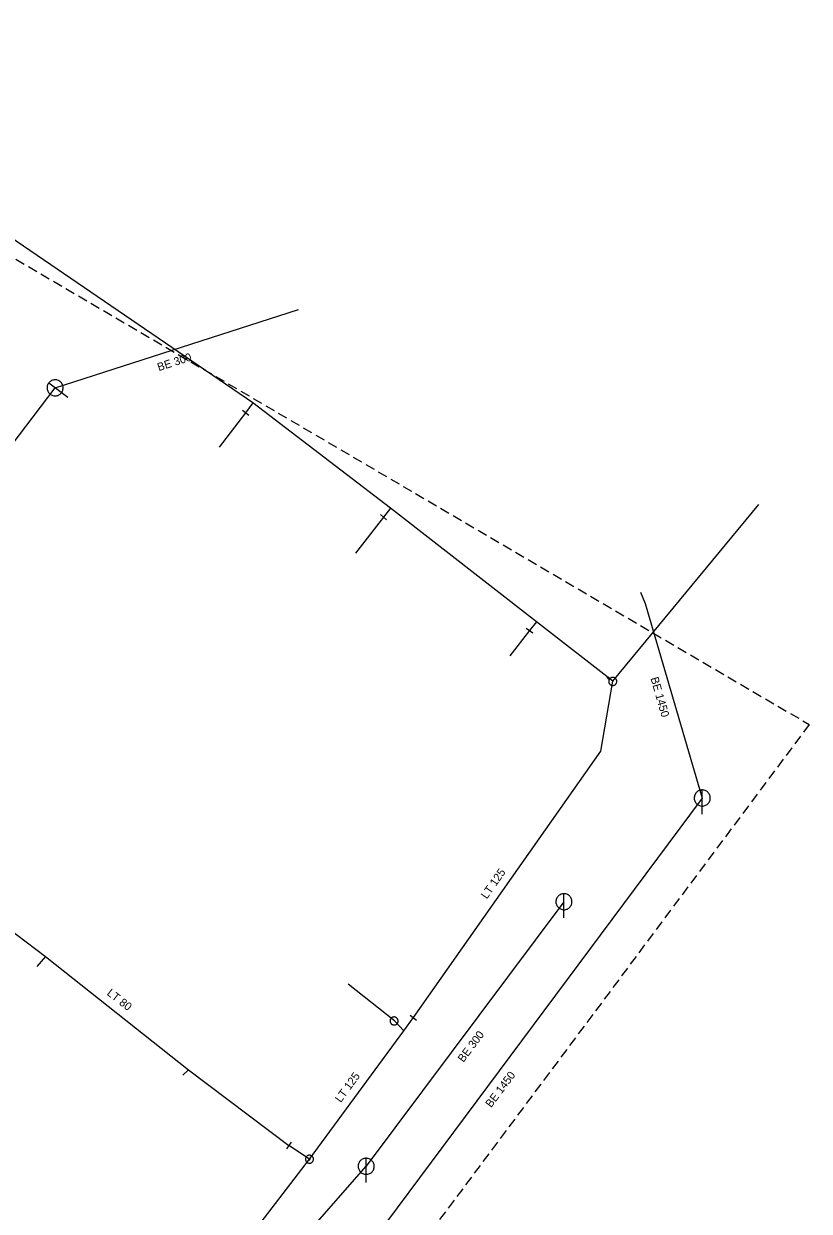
# Model space of a CAD drawing. Extents: x -791337 to -790755, y -988454 to -987923.
# Drawn here: x -790852.8 to -790755.1, y -988262.8 to -988115.1 of the extents above; entities that cross this region are included whole.
import ezdxf

# ---------------------------------------------------------------- set-up
doc = ezdxf.new("R2010")
doc.units = 0
doc.header["$LTSCALE"] = 0.4
doc.linetypes.add('MEDIUM_DASHED', pattern=[4.5, 3, -1.5])
for name, color, linetype, lineweight in [('1', 7, 'Continuous', 13), ('13', 7, 'Continuous', 13), ('14', 7, 'Continuous', 25), ('17', 7, 'Continuous', 25), ('22', 7, 'Continuous', 13), ('23', 7, 'Continuous', 13), ('34', 7, 'Continuous', 13), ('47', 7, 'Continuous', 13), ('63', 7, 'MEDIUM_DASHED', 25)]:
    doc.layers.add(name, color=color, linetype=linetype, lineweight=lineweight)

msp = doc.modelspace()

# ---------------------------------------------------------------- linework, layer by layer
at = {"layer": '13'}
for p, q in [((-790824.261, -988162.25), (-790825.189, -988163.508)), ((-790825.189, -988163.508), (-790828.463, -988167.789)), ((-790808.039, -988176.499), (-790811.535, -988180.96)), ((-790807.158, -988175.363), (-790808.039, -988176.499)), ((-790789.015, -988189.477), (-790789.888, -988190.568)), ((-790789.888, -988190.568), (-790792.35, -988193.728)), ((-790850.055, -988231.078), (-790851.113, -988232.317)), ((-790832.26, -988245.158), (-790832.993, -988245.852))]:
    msp.add_line(p, q, dxfattribs=at)
msp.add_lwpolyline([(-790805.532, -988240.335), (-790806.689, -988239.099), (-790812.443, -988234.541)], dxfattribs=at)
at = {"layer": '14'}
for p, q in [((-790848.859, -988160.41), (-790818.585, -988150.648)), ((-790872.25, -988191.129), (-790848.859, -988160.41)), ((-790768.42, -988211.39), (-790819.92, -988280.52)), ((-790785.61, -988224.28), (-790810.19, -988257.17)), ((-790834.989, -988285.46), (-790810.19, -988257.17))]:
    msp.add_line(p, q, dxfattribs=at)
at = {"layer": '14', "lineweight": 13}
msp.add_line((-790817.244, -988256.29), (-790819.799, -988254.598), dxfattribs=at)
at = {"layer": '14'}
msp.add_lwpolyline([(-790776.109, -988185.784), (-790775.515, -988187.214), (-790768.42, -988211.39)], dxfattribs=at)
at = {"layer": '17'}
for p, q in [((-790779.549, -988196.869), (-790761.405, -988174.91)), ((-790834.335, -988278.502), (-790817.244, -988256.29))]:
    msp.add_line(p, q, dxfattribs=at)
for points in [[(-790779.549, -988196.869), (-790789.015, -988189.477), (-790807.158, -988175.363), (-790824.261, -988162.25), (-790868.789, -988131.909)], [(-790804.318, -988238.685), (-790781.01, -988205.579), (-790779.549, -988196.869)], [(-790865.725, -988219.221), (-790850.055, -988231.078), (-790832.26, -988245.158), (-790819.799, -988254.598)], [(-790817.244, -988256.29), (-790805.532, -988240.335), (-790804.318, -988238.685)]]:
    msp.add_lwpolyline(points, dxfattribs=at)
at = {"layer": '22'}
for p, q in [((-790847.261, -988161.613), (-790849.657, -988159.808)), ((-790768.42, -988213.39), (-790768.419, -988210.39)), ((-790785.61, -988226.28), (-790785.609, -988223.28)), ((-790810.19, -988259.17), (-790810.189, -988256.17))]:
    msp.add_line(p, q, dxfattribs=at)
for points in [[(-790848.256, -988159.611), (-790848.347, -988159.55), (-790848.444, -988159.5), (-790848.547, -988159.46), (-790848.652, -988159.431), (-790848.76, -988159.414), (-790848.87, -988159.41), (-790848.979, -988159.417), (-790849.086, -988159.437), (-790849.192, -988159.467), (-790849.293, -988159.509), (-790849.389, -988159.562), (-790849.478, -988159.626), (-790849.56, -988159.698), (-790849.634, -988159.779), (-790849.698, -988159.868), (-790849.752, -988159.963), (-790849.797, -988160.063), (-790849.829, -988160.168), (-790849.849, -988160.276), (-790849.858, -988160.384), (-790849.854, -988160.494), (-790849.839, -988160.602), (-790849.812, -988160.709), (-790849.774, -988160.811), (-790849.725, -988160.909), (-790849.665, -988161), (-790849.595, -988161.085), (-790849.517, -988161.162), (-790849.43, -988161.229), (-790849.337, -988161.287), (-790849.239, -988161.335), (-790849.136, -988161.37), (-790849.029, -988161.395), (-790848.92, -988161.408), (-790848.81, -988161.409), (-790848.702, -988161.398), (-790848.595, -988161.375), (-790848.491, -988161.34), (-790848.392, -988161.295), (-790848.297, -988161.238), (-790848.21, -988161.172), (-790848.131, -988161.097), (-790848.06, -988161.012), (-790847.999, -988160.922), (-790847.949, -988160.825), (-790847.909, -988160.723), (-790847.88, -988160.617), (-790847.863, -988160.508), (-790847.858, -988160.399), (-790847.865, -988160.29), (-790847.884, -988160.182), (-790847.915, -988160.077), (-790847.957, -988159.976), (-790848.01, -988159.881), (-790848.073, -988159.791), (-790848.146, -988159.708), (-790848.227, -988159.635)], [(-790767.42, -988211.39), (-790767.425, -988211.281), (-790767.443, -988211.173), (-790767.473, -988211.067), (-790767.513, -988210.966), (-790767.565, -988210.869), (-790767.627, -988210.779), (-790767.699, -988210.696), (-790767.779, -988210.622), (-790767.867, -988210.556), (-790767.961, -988210.501), (-790768.061, -988210.456), (-790768.166, -988210.423), (-790768.273, -988210.401), (-790768.382, -988210.391), (-790768.492, -988210.393), (-790768.6, -988210.407), (-790768.707, -988210.432), (-790768.81, -988210.469), (-790768.908, -988210.518), (-790769, -988210.576), (-790769.086, -988210.645), (-790769.163, -988210.722), (-790769.232, -988210.808), (-790769.291, -988210.9), (-790769.339, -988210.998), (-790769.376, -988211.101), (-790769.402, -988211.208), (-790769.416, -988211.316), (-790769.419, -988211.426), (-790769.409, -988211.535), (-790769.388, -988211.642), (-790769.354, -988211.746), (-790769.31, -988211.846), (-790769.255, -988211.941), (-790769.189, -988212.029), (-790769.115, -988212.109), (-790769.032, -988212.181), (-790768.942, -988212.243), (-790768.846, -988212.295), (-790768.744, -988212.336), (-790768.639, -988212.366), (-790768.531, -988212.384), (-790768.421, -988212.39), (-790768.312, -988212.384), (-790768.204, -988212.366), (-790768.099, -988212.337), (-790767.997, -988212.296), (-790767.9, -988212.244), (-790767.81, -988212.182), (-790767.727, -988212.111), (-790767.652, -988212.031), (-790767.587, -988211.943), (-790767.531, -988211.849), (-790767.487, -988211.749), (-790767.453, -988211.645), (-790767.431, -988211.537), (-790767.421, -988211.428)], [(-790784.61, -988224.28), (-790784.615, -988224.171), (-790784.633, -988224.063), (-790784.663, -988223.957), (-790784.703, -988223.856), (-790784.755, -988223.759), (-790784.817, -988223.669), (-790784.889, -988223.586), (-790784.969, -988223.512), (-790785.057, -988223.446), (-790785.151, -988223.391), (-790785.251, -988223.346), (-790785.356, -988223.313), (-790785.463, -988223.291), (-790785.572, -988223.281), (-790785.682, -988223.283), (-790785.79, -988223.297), (-790785.897, -988223.322), (-790786, -988223.359), (-790786.098, -988223.408), (-790786.19, -988223.466), (-790786.276, -988223.535), (-790786.353, -988223.612), (-790786.422, -988223.698), (-790786.481, -988223.79), (-790786.529, -988223.888), (-790786.566, -988223.991), (-790786.592, -988224.098), (-790786.606, -988224.206), (-790786.609, -988224.316), (-790786.599, -988224.425), (-790786.578, -988224.532), (-790786.544, -988224.636), (-790786.5, -988224.736), (-790786.445, -988224.831), (-790786.379, -988224.919), (-790786.305, -988224.999), (-790786.222, -988225.071), (-790786.132, -988225.133), (-790786.036, -988225.185), (-790785.934, -988225.226), (-790785.829, -988225.256), (-790785.721, -988225.274), (-790785.611, -988225.28), (-790785.502, -988225.274), (-790785.394, -988225.256), (-790785.289, -988225.227), (-790785.187, -988225.186), (-790785.09, -988225.134), (-790785, -988225.072), (-790784.917, -988225.001), (-790784.842, -988224.921), (-790784.777, -988224.833), (-790784.721, -988224.739), (-790784.677, -988224.639), (-790784.643, -988224.535), (-790784.621, -988224.427), (-790784.611, -988224.318)], [(-790809.19, -988257.17), (-790809.195, -988257.061), (-790809.213, -988256.953), (-790809.243, -988256.847), (-790809.283, -988256.746), (-790809.335, -988256.649), (-790809.397, -988256.559), (-790809.469, -988256.476), (-790809.549, -988256.402), (-790809.637, -988256.336), (-790809.731, -988256.281), (-790809.831, -988256.236), (-790809.936, -988256.203), (-790810.043, -988256.181), (-790810.152, -988256.171), (-790810.262, -988256.173), (-790810.37, -988256.187), (-790810.477, -988256.212), (-790810.58, -988256.249), (-790810.678, -988256.298), (-790810.77, -988256.356), (-790810.856, -988256.425), (-790810.933, -988256.502), (-790811.002, -988256.588), (-790811.061, -988256.68), (-790811.109, -988256.778), (-790811.146, -988256.881), (-790811.172, -988256.988), (-790811.186, -988257.096), (-790811.189, -988257.206), (-790811.179, -988257.315), (-790811.158, -988257.422), (-790811.124, -988257.526), (-790811.08, -988257.626), (-790811.025, -988257.721), (-790810.959, -988257.809), (-790810.885, -988257.889), (-790810.802, -988257.961), (-790810.712, -988258.023), (-790810.616, -988258.075), (-790810.514, -988258.116), (-790810.409, -988258.146), (-790810.301, -988258.164), (-790810.191, -988258.17), (-790810.082, -988258.164), (-790809.974, -988258.146), (-790809.869, -988258.117), (-790809.767, -988258.076), (-790809.67, -988258.024), (-790809.58, -988257.962), (-790809.497, -988257.891), (-790809.422, -988257.811), (-790809.357, -988257.723), (-790809.301, -988257.629), (-790809.257, -988257.529), (-790809.223, -988257.425), (-790809.201, -988257.317), (-790809.191, -988257.208)]]:
    msp.add_lwpolyline(points, close=True, dxfattribs=at)
at = {"layer": '23'}
msp.add_line((-790780.015, -988196.411), (-790780.132, -988196.568), dxfattribs=at)
for points in [[(-790780.055, -988196.626), (-790780.174, -988196.536), (-790780.235, -988196.366), (-790780.056, -988196.38), (-790779.937, -988196.469)], [(-790779.248, -988196.498), (-790779.292, -988196.468), (-790779.339, -988196.444), (-790779.387, -988196.427), (-790779.438, -988196.412), (-790779.489, -988196.404), (-790779.542, -988196.402), (-790779.594, -988196.404), (-790779.645, -988196.412), (-790779.696, -988196.425), (-790779.745, -988196.443), (-790779.792, -988196.466), (-790779.837, -988196.496), (-790779.877, -988196.528), (-790779.913, -988196.564), (-790779.947, -988196.604), (-790779.976, -988196.65), (-790780, -988196.694), (-790780.019, -988196.745), (-790780.033, -988196.793), (-790780.042, -988196.845), (-790780.044, -988196.899), (-790780.041, -988196.951), (-790780.033, -988197.003), (-790780.021, -988197.054), (-790780.002, -988197.102), (-790779.978, -988197.149), (-790779.95, -988197.192), (-790779.917, -988197.233), (-790779.88, -988197.27), (-790779.84, -988197.304), (-790779.796, -988197.333), (-790779.749, -988197.357), (-790779.7, -988197.376), (-790779.651, -988197.39), (-790779.6, -988197.397), (-790779.547, -988197.4), (-790779.494, -988197.398), (-790779.442, -988197.39), (-790779.392, -988197.377)], [(-790780.019, -988196.745), (-790780.033, -988196.793), (-790780.042, -988196.845), (-790780.044, -988196.899), (-790780.041, -988196.951), (-790780.033, -988197.003), (-790780.021, -988197.054), (-790780.002, -988197.102), (-790779.978, -988197.149), (-790779.95, -988197.192), (-790779.917, -988197.233), (-790779.88, -988197.27), (-790779.84, -988197.304), (-790779.796, -988197.333), (-790779.749, -988197.357), (-790779.7, -988197.376), (-790779.651, -988197.39), (-790779.6, -988197.397), (-790779.547, -988197.4), (-790779.494, -988197.398), (-790779.442, -988197.39), (-790779.392, -988197.377), (-790779.343, -988197.359), (-790779.296, -988197.334), (-790779.252, -988197.307), (-790779.211, -988197.273), (-790779.175, -988197.236), (-790779.142, -988197.197), (-790779.114, -988197.153), (-790779.089, -988197.106), (-790779.069, -988197.057), (-790779.056, -988197.007), (-790779.047, -988196.955), (-790779.044, -988196.904), (-790779.048, -988196.851), (-790779.054, -988196.799), (-790779.068, -988196.749), (-790779.087, -988196.699), (-790779.11, -988196.652), (-790779.139, -988196.609)], [(-790779.392, -988197.377), (-790779.343, -988197.359), (-790779.296, -988197.334), (-790779.252, -988197.307), (-790779.211, -988197.273), (-790779.175, -988197.236), (-790779.142, -988197.197), (-790779.114, -988197.153), (-790779.089, -988197.106), (-790779.069, -988197.057), (-790779.056, -988197.007), (-790779.047, -988196.955), (-790779.044, -988196.904), (-790779.048, -988196.851), (-790779.054, -988196.799), (-790779.068, -988196.749), (-790779.087, -988196.699), (-790779.11, -988196.652), (-790779.139, -988196.609), (-790779.172, -988196.568), (-790779.208, -988196.531), (-790779.248, -988196.498), (-790779.292, -988196.468), (-790779.339, -988196.444), (-790779.387, -988196.427), (-790779.438, -988196.412), (-790779.489, -988196.404), (-790779.542, -988196.402), (-790779.594, -988196.404), (-790779.645, -988196.412), (-790779.696, -988196.425), (-790779.745, -988196.443), (-790779.792, -988196.466), (-790779.837, -988196.496), (-790779.877, -988196.528), (-790779.913, -988196.564), (-790779.947, -988196.604), (-790779.976, -988196.65), (-790780, -988196.694), (-790780.019, -988196.745)], [(-790779.139, -988196.609), (-790779.172, -988196.568), (-790779.208, -988196.531), (-790779.248, -988196.498)], [(-790806.325, -988239.408), (-790806.295, -988239.365), (-790806.27, -988239.319), (-790806.251, -988239.271), (-790806.235, -988239.221), (-790806.226, -988239.17), (-790806.222, -988239.117), (-790806.223, -988239.065), (-790806.23, -988239.014), (-790806.241, -988238.962), (-790806.258, -988238.913), (-790806.28, -988238.865), (-790806.308, -988238.82), (-790806.339, -988238.779), (-790806.375, -988238.741), (-790806.414, -988238.707), (-790806.459, -988238.676), (-790806.503, -988238.652), (-790806.553, -988238.631), (-790806.601, -988238.616), (-790806.653, -988238.606), (-790806.706, -988238.603), (-790806.758, -988238.604), (-790806.811, -988238.61), (-790806.862, -988238.621), (-790806.91, -988238.639), (-790806.958, -988238.662), (-790807.002, -988238.689), (-790807.044, -988238.721), (-790807.081, -988238.757), (-790807.116, -988238.796), (-790807.146, -988238.839), (-790807.171, -988238.885), (-790807.192, -988238.934), (-790807.207, -988238.983), (-790807.215, -988239.034), (-790807.22, -988239.086), (-790807.219, -988239.139), (-790807.213, -988239.192), (-790807.2, -988239.242)], [(-790806.553, -988238.631), (-790806.601, -988238.616), (-790806.653, -988238.606), (-790806.706, -988238.603), (-790806.758, -988238.604), (-790806.811, -988238.61), (-790806.862, -988238.621), (-790806.91, -988238.639), (-790806.958, -988238.662), (-790807.002, -988238.689), (-790807.044, -988238.721), (-790807.081, -988238.757), (-790807.116, -988238.796), (-790807.146, -988238.839), (-790807.171, -988238.885), (-790807.192, -988238.934), (-790807.207, -988238.983), (-790807.215, -988239.034), (-790807.22, -988239.086), (-790807.219, -988239.139), (-790807.213, -988239.192), (-790807.2, -988239.242), (-790807.184, -988239.291), (-790807.161, -988239.339), (-790807.135, -988239.383), (-790807.102, -988239.425), (-790807.066, -988239.462), (-790807.027, -988239.497), (-790806.984, -988239.526), (-790806.938, -988239.552), (-790806.889, -988239.573), (-790806.839, -988239.587), (-790806.788, -988239.597), (-790806.737, -988239.602), (-790806.683, -988239.599), (-790806.632, -988239.594), (-790806.582, -988239.582), (-790806.531, -988239.565), (-790806.484, -988239.542), (-790806.439, -988239.515)], [(-790807.2, -988239.242), (-790807.184, -988239.291), (-790807.161, -988239.339), (-790807.135, -988239.383), (-790807.102, -988239.425), (-790807.066, -988239.462), (-790807.027, -988239.497), (-790806.984, -988239.526), (-790806.938, -988239.552), (-790806.889, -988239.573), (-790806.839, -988239.587), (-790806.788, -988239.597), (-790806.737, -988239.602), (-790806.683, -988239.599), (-790806.632, -988239.594), (-790806.582, -988239.582), (-790806.531, -988239.565), (-790806.484, -988239.542), (-790806.439, -988239.515), (-790806.398, -988239.482), (-790806.36, -988239.447), (-790806.325, -988239.408), (-790806.295, -988239.365), (-790806.27, -988239.319), (-790806.251, -988239.271), (-790806.235, -988239.221), (-790806.226, -988239.17), (-790806.222, -988239.117), (-790806.223, -988239.065), (-790806.23, -988239.014), (-790806.241, -988238.962), (-790806.258, -988238.913), (-790806.28, -988238.865), (-790806.308, -988238.82), (-790806.339, -988238.779), (-790806.375, -988238.741), (-790806.414, -988238.707), (-790806.459, -988238.676), (-790806.503, -988238.652), (-790806.553, -988238.631)], [(-790806.439, -988239.515), (-790806.398, -988239.482), (-790806.36, -988239.447), (-790806.325, -988239.408)]]:
    msp.add_lwpolyline(points, dxfattribs=at)
at = {"layer": '34'}
for p, q in [((-790825.583, -988163.2), (-790824.795, -988163.816)), ((-790808.415, -988176.17), (-790807.662, -988176.828)), ((-790790.285, -988190.265), (-790789.49, -988190.871)), ((-790804.711, -988238.376), (-790803.924, -988238.994)), ((-790819.511, -988254.188), (-790820.086, -988255.006))]:
    msp.add_line(p, q, dxfattribs=at)
at = {"layer": '47'}
for points in [[(-790816.897, -988256.65), (-790816.861, -988256.611), (-790816.829, -988256.57), (-790816.803, -988256.525), (-790816.78, -988256.478), (-790816.763, -988256.428), (-790816.751, -988256.377), (-790816.746, -988256.325), (-790816.745, -988256.273), (-790816.749, -988256.221), (-790816.758, -988256.169), (-790816.774, -988256.119), (-790816.795, -988256.071), (-790816.819, -988256.025), (-790816.849, -988255.982), (-790816.883, -988255.943), (-790816.922, -988255.907), (-790816.963, -988255.875), (-790817.009, -988255.848), (-790817.055, -988255.826), (-790817.105, -988255.809), (-790817.156, -988255.797), (-790817.209, -988255.791), (-790817.261, -988255.79), (-790817.313, -988255.794), (-790817.364, -988255.804), (-790817.414, -988255.82), (-790817.463, -988255.84), (-790817.508, -988255.865), (-790817.551, -988255.895), (-790817.59, -988255.929), (-790817.626, -988255.968), (-790817.658, -988256.009), (-790817.685, -988256.054), (-790817.707, -988256.101), (-790817.724, -988256.151), (-790817.736, -988256.202), (-790817.743, -988256.254), (-790817.744, -988256.306), (-790817.739, -988256.359), (-790817.729, -988256.41), (-790817.713, -988256.46), (-790817.694, -988256.508), (-790817.668, -988256.554), (-790817.638, -988256.597), (-790817.604, -988256.636), (-790817.565, -988256.672), (-790817.524, -988256.704), (-790817.48, -988256.731), (-790817.432, -988256.753), (-790817.382, -988256.77), (-790817.331, -988256.782), (-790817.28, -988256.788), (-790817.227, -988256.789), (-790817.175, -988256.784), (-790817.123, -988256.775), (-790817.073, -988256.759), (-790817.026, -988256.739), (-790816.979, -988256.714), (-790816.936, -988256.684)], [(-790817.187, -988256.349), (-790817.18, -988256.342), (-790817.176, -988256.335), (-790817.171, -988256.328), (-790817.168, -988256.321), (-790817.165, -988256.312), (-790817.163, -988256.304), (-790817.162, -988256.295), (-790817.161, -988256.287), (-790817.163, -988256.278), (-790817.164, -988256.27), (-790817.167, -988256.261), (-790817.17, -988256.253), (-790817.174, -988256.246), (-790817.178, -988256.239), (-790817.184, -988256.233), (-790817.191, -988256.226), (-790817.198, -988256.222), (-790817.205, -988256.217), (-790817.212, -988256.214), (-790817.221, -988256.211), (-790817.229, -988256.209), (-790817.238, -988256.208), (-790817.246, -988256.207), (-790817.255, -988256.208), (-790817.263, -988256.21), (-790817.272, -988256.213), (-790817.28, -988256.216), (-790817.287, -988256.22), (-790817.294, -988256.224), (-790817.3, -988256.23), (-790817.307, -988256.237), (-790817.311, -988256.244), (-790817.316, -988256.251), (-790817.319, -988256.258), (-790817.322, -988256.267), (-790817.325, -988256.275), (-790817.325, -988256.284), (-790817.326, -988256.292), (-790817.325, -988256.301), (-790817.323, -988256.309), (-790817.32, -988256.318), (-790817.317, -988256.326), (-790817.313, -988256.333), (-790817.309, -988256.34), (-790817.303, -988256.346), (-790817.296, -988256.353), (-790817.289, -988256.357), (-790817.282, -988256.362), (-790817.275, -988256.365), (-790817.266, -988256.368), (-790817.258, -988256.371), (-790817.249, -988256.371), (-790817.241, -988256.372), (-790817.232, -988256.37), (-790817.224, -988256.369), (-790817.215, -988256.366), (-790817.207, -988256.363), (-790817.2, -988256.359), (-790817.193, -988256.355)]]:
    msp.add_lwpolyline(points, close=True, dxfattribs=at)
at = {"layer": '63'}
msp.add_lwpolyline([(-791231.02, -987923.132), (-790755.118, -988202.253), (-790755.118, -988202.253), (-790903.053, -988400.429), (-790903.053, -988400.429), (-791331.504, -988073.857), (-791331.504, -988073.857)], close=True, dxfattribs=at)

# ---------------------------------------------------------------- texts
at = {"layer": '1'}
for s, rotation, p in [('BE 300', 18, (-790835.968, -988158.339)), ('BE 1450 ', 286, (-790774.858, -988196.502)), ('LT 125', 55, (-790795.196, -988224.017)), ('LT 80 ', 322, (-790842.505, -988235.793)), ('BE 300', 53, (-790798.105, -988244.316)), ('LT 125', 54, (-790813.352, -988249.321)), ('BE 1450 ', 53, (-790794.667, -988249.947))]:
    msp.add_text(s, height=1, rotation=rotation, dxfattribs=at).set_placement(p)

doc.saveas('drawing.dxf')
